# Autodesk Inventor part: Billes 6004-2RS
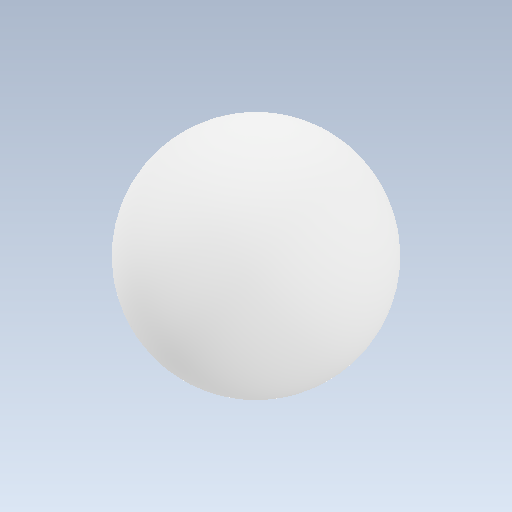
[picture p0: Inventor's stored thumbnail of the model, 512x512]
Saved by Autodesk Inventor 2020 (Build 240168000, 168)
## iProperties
Created: 2003-07
Part Number: Billes 6004-2RS
Material: Générique
Document SubType Name: Modeling
Designer: Bruno
Density: 1 g/cm^3
Appearance: Par défaut
Author: Bruno
Sending System: SolidWorks 2011
Last Author: frederic
Last Saved: 2012-02-20
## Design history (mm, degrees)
feature "Base-Révolution"
node "Solide1"
